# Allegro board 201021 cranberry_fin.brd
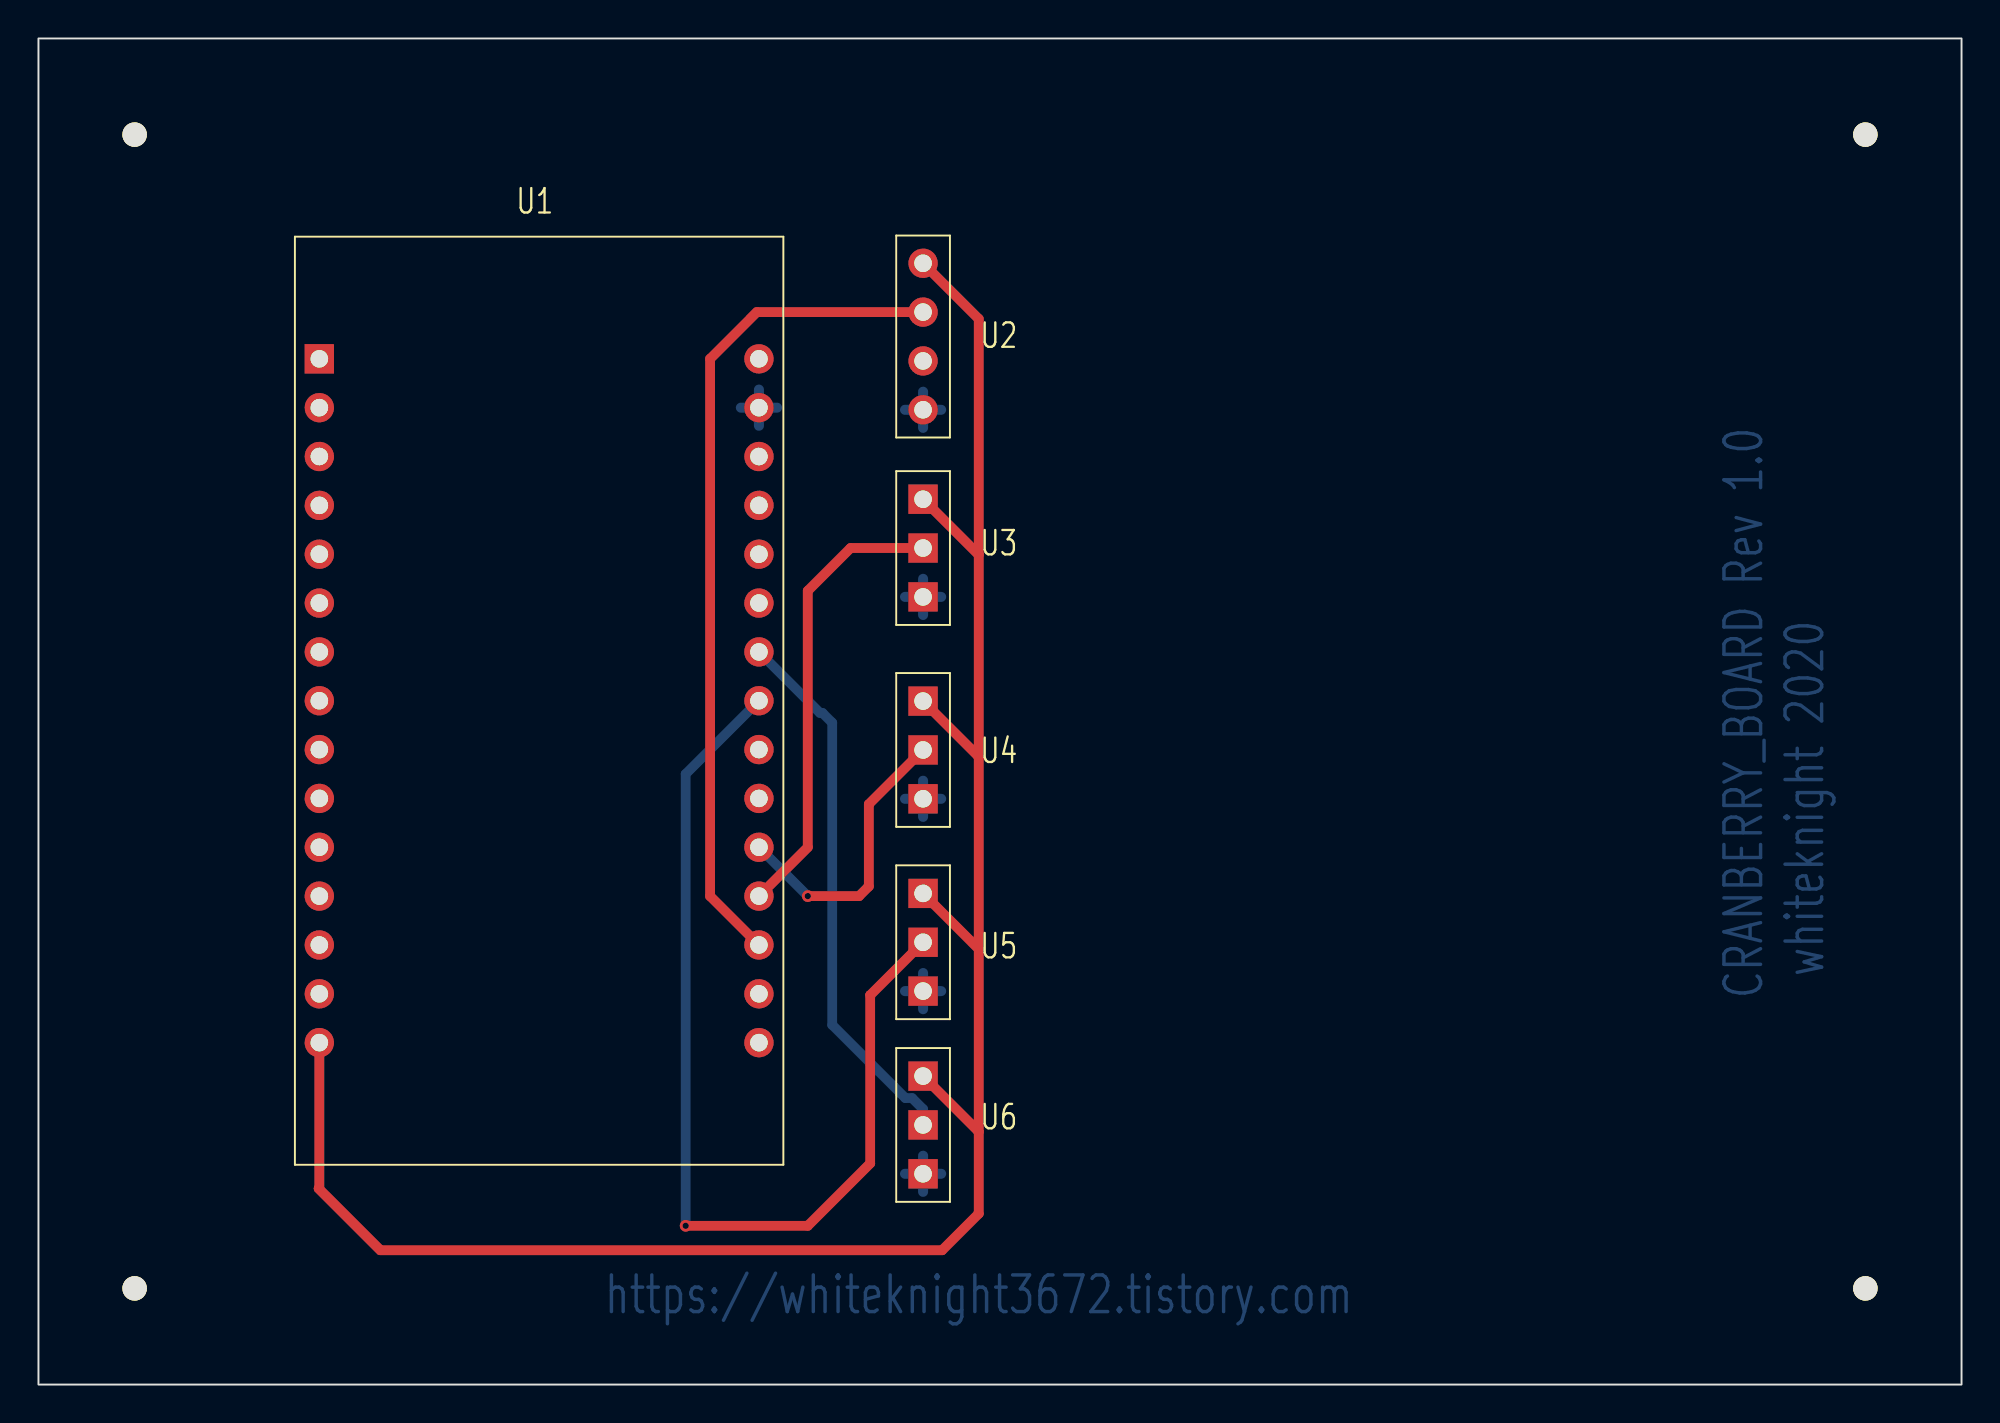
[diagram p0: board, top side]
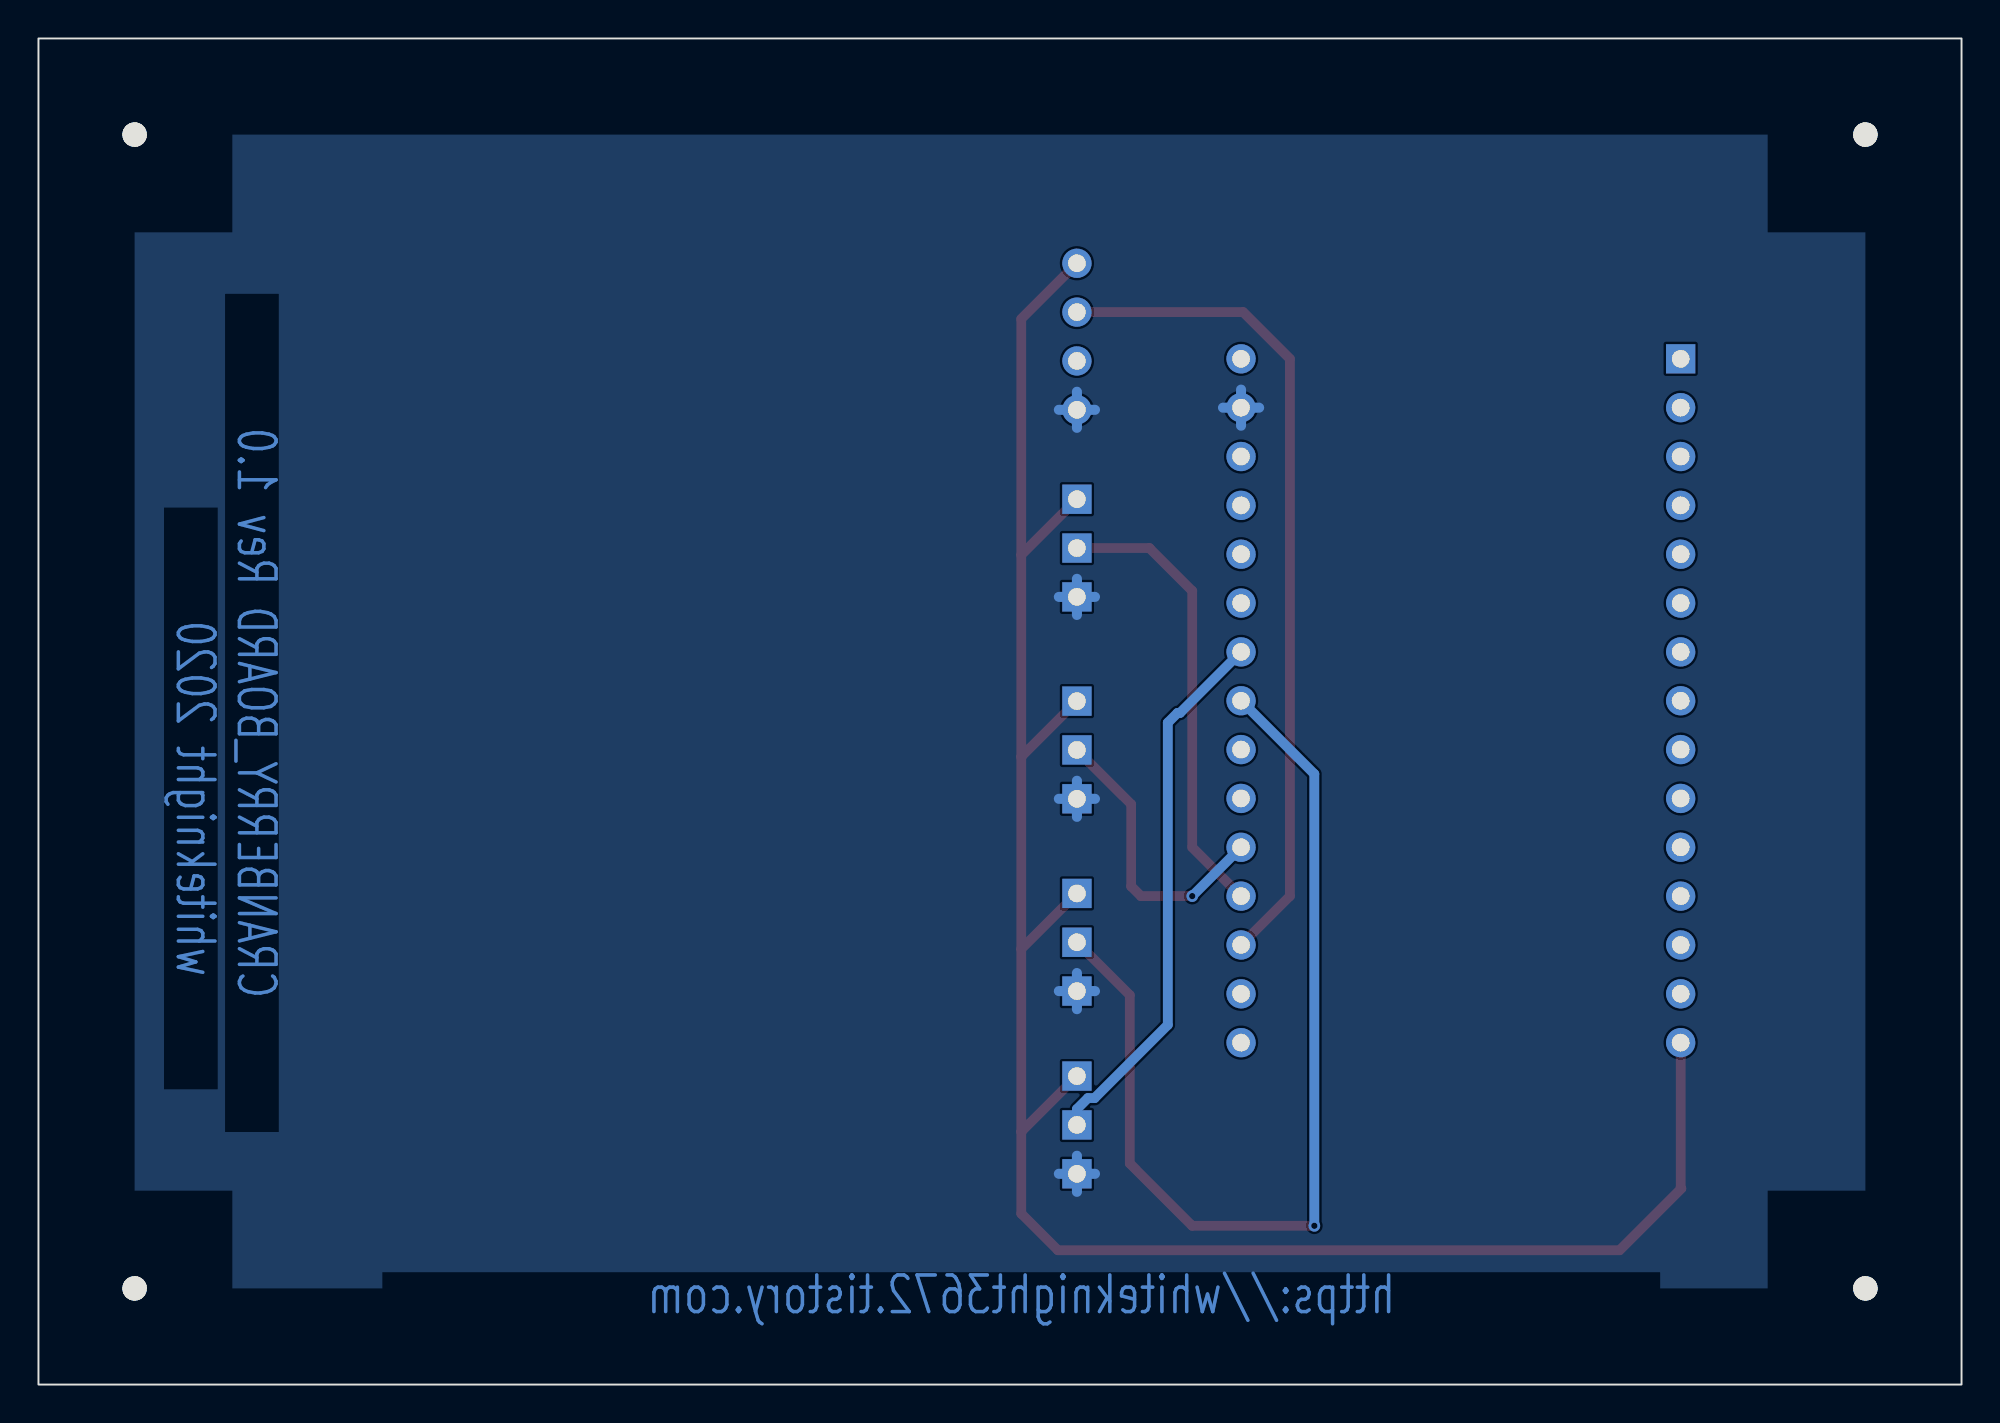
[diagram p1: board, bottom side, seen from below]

Outline 100 x 70 mm; copper layers: TOP, BOTTOM. Coordinates in mm from the lower left corner of the outline.
Outline path: rectangle 0,0 100,70

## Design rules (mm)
constraint set DEFAULT: min track width 0.508

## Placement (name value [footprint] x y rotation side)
NOREF  -  [unnamed]  95 5 0 top
NOREF#2  -  [unnamed]  5 65 0 top
NOREF#3  -  [unnamed]  5 5 0 top
NOREF#4  -  [unnamed]  95 65 0 top
U1  NODEMCU  [ESP12]  26.04 35.56 0 top
U2  AM2302  [DHT22]  46 54.5 0 top
U3  KY-022  [REL01]  46 43.5 0 top
U4  RELAY  [REL01]  46 33 0 top
U5  RELAY  [REL01]  46 23 0 top
U6  MOTION_SENSOR  [REL01]  46 13.5 0 top

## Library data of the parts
U1 = nodemcu
U2 = AM2302
U3-U6 = COMMON_PART

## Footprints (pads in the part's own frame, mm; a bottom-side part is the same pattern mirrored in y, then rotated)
DHT22
  round 1.524 hole 0.914: 1(0,3.81) 2(0,1.27) 3(0,-1.27) 4(0,-3.81)
ESP12
  rect 1.524x1.524 hole 0.914: 1(-11.43,17.78)
  round 1.524 hole 0.914: 2(-11.43,15.24) 3(-11.43,12.7) 4(-11.43,10.16) 5(-11.43,7.62) 6(-11.43,5.08) 7(-11.43,2.54) 8(-11.43,0) 9(-11.43,-2.54) 10(-11.43,-5.08) 11(-11.43,-7.62) 12(-11.43,-10.16) 13(-11.43,-12.7) 14(-11.43,-15.24) 15(-11.43,-17.78) 16(11.43,-17.78) 17(11.43,-15.24) 18(11.43,-12.7) 19(11.43,-10.16) 20(11.43,-7.62) 21(11.43,-5.08) 22(11.43,-2.54) 23(11.43,0) 24(11.43,2.54) 25(11.43,5.08) 26(11.43,7.62) 27(11.43,10.16) 28(11.43,12.7) 29(11.43,15.24) 30(11.43,17.78)
REL01
  rect 1.524x1.524 hole 0.914: 1(0,2.54) 2(0,0) 3(0,-2.54)
unnamed
  round 1.27 hole 6.35 unplated: (0,0)

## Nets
N00270: U1.15(VIN) U2.1(VCC) U3.1(VCC) U4.1(VCC) U5.1(VCC) U6.1(VCC)
N00353: U1.29 U2.4 U3.3 U4.3 U5.3 U6.3
N00843: U1.18 U2.2
N00887: U1.19 U3.2
N00891: U1.20 U4.2
N00950: U1.23 U5.2
N01004: U1.24 U6.2

Pads without a net: U1 1 2 3 4 5 6 7 8 9 10 11 12 13 14 16 17 21 22 25 26 27 28 30; U2 3

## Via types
v1: diameter 0.61, hole 0.33, TOP to BOTTOM, 3 vias

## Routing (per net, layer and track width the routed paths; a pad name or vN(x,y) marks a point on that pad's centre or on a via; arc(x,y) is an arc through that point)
N00270: length 111
  TOP w0.508: 48.9,22.64 48.9,13.14 ; 48.9,22.64 48.9,32.65 ; 48.9,22.64 U5.1 ; 48.9,13.14 48.9,8.89 46.99,6.99 17.78,6.99 14.57,10.2 14.61,10.23 U1.15 ; 48.9,13.14 U6.1 ; 48.9,43.15 U3.1 ; 48.9,43.15 48.9,55.41 U2.1 ; 48.9,43.15 48.9,32.65 ; 48.9,32.65 U4.1
N00353: length 22.6
  BOTTOM w0.521: 45.06,30.46 U4.3 ; U4.3 46,29.52 ; U4.3 46,31.4 ; U4.3 46.94,30.46 ; U3.3 46,41.9 ; U3.3 45.06,40.96 ; U3.3 46.94,40.96 ; U3.3 46,40.02 ; U5.3 46.94,20.46 ; U5.3 46,21.4 ; U5.3 46,19.52 ; U5.3 45.06,20.46 ; 36.52,50.8 U1.29 ; U1.29 38.41,50.8 ; U1.29 37.47,51.74 ; U1.29 37.47,49.86 ; U6.3 46,11.9 ; U6.3 46,10.02 ; U6.3 46.94,10.96 ; U6.3 45.06,10.96 ; U2.4 46,51.63 ; U2.4 45.06,50.69 ; U2.4 46,49.75 ; U2.4 46.94,50.69
N00843: length 43.6
  TOP w0.508: U2.2 37.35,55.77 34.92,53.34 34.92,25.4 U1.18
N00887: length 23.8
  TOP w0.508: U1.19 40.01,27.94 40.01,41.27 42.23,43.5 U3.2
N00891: length 15.2
  TOP w0.508: U4.2 43.18,30.18 43.18,25.91 42.67,25.4 v1(40.01,25.4)
  BOTTOM w0.508: U1.20 v1(40.01,25.4)
N00950: length 52.5
  TOP w0.508: U5.2 43.25,20.25 43.25,11.5 40.01,8.26 v1(33.66,8.26)
  BOTTOM w0.508: v1(33.66,8.26) 33.66,31.75 U1.23
N01004: length 28.4
  BOTTOM w0.508: U1.24 40.64,34.92 40.77,34.92 41.27,34.42 41.27,18.7 45.08,14.9 45.43,14.9 46,14.32 v1(46,13.5)

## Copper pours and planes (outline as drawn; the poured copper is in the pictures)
N00353 on BOTTOM: 5,5 5,65 95,65 95,5

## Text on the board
BOTTOM: https://whiteknight3672.tistory.com | CRANBERRY_BOARD Rev 1.0 | whiteknight 2020
